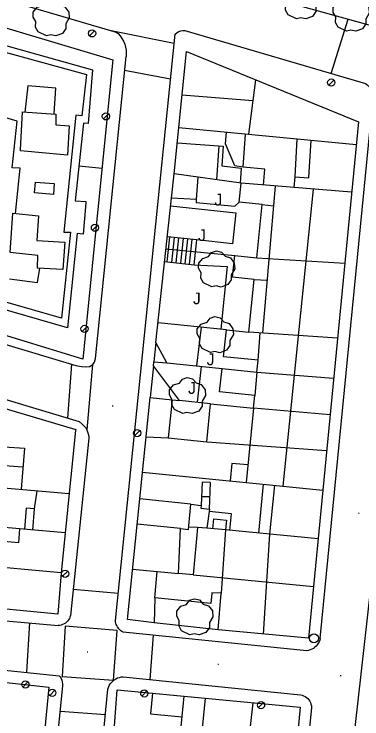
# Model space of a CAD drawing. Extents: x 431390 to 432653, y 4586754 to 4589600.
# Drawn here: x 432037.9 to 432076.5, y 4587457.3 to 4587535.4 of the extents above; entities that cross this region are included whole.
import ezdxf

# ---------------------------------------------------------------- set-up
doc = ezdxf.new("R2010")
doc.units = 0
for name, color, linetype in [('COM_17LS_LN', 7, 'Continuous'), ('COM_51_LN', 7, 'Continuous'), ('CON_01_LN', 7, 'Continuous'), ('CON_01FI_LN', 7, 'Continuous'), ('CON_03_LN', 7, 'Continuous'), ('CON_04_LN', 7, 'Continuous'), ('CON_07_LN', 7, 'Continuous'), ('CON_16_LN', 7, 'Continuous'), ('CON_23_LN', 7, 'Continuous'), ('CON_29_LN', 7, 'Continuous'), ('ENE_05_PT', 7, 'Continuous'), ('ENE_06_PT', 7, 'Continuous'), ('ORO_03_PT', 7, 'Continuous'), ('TOP_15JA_TX', 7, 'Continuous'), ('VEG_03_PT', 7, 'Continuous'), ('VEG_06_LN', 7, 'Continuous')]:
    doc.layers.add(name, color=color, linetype=linetype)

msp = doc.modelspace()

# ---------------------------------------------------------------- linework, layer by layer
at = {"layer": 'COM_17LS_LN'}
for points in [[(432021.761, 4587589.102), (432009.412, 4587553.409), (432035.816, 4587545.686), (432076.824, 4587534.291), (432119.906, 4587522.114), (432137.525, 4587517.191)], [(432010.743, 4587544.715), (432049.243, 4587533.403)], [(432049.175, 4587468.233), (432055.778, 4587533.151)], [(432049.243, 4587533.403), (432049.454, 4587533.22), (432049.687, 4587532.965), (432049.89, 4587532.684), (432050.058, 4587532.382), (432050.191, 4587532.062), (432050.287, 4587531.729), (432050.343, 4587531.388), (432050.36, 4587531.042), (432050.337, 4587530.697)], [(432055.778, 4587533.151), (432056.002, 4587533.342), (432056.194, 4587533.45), (432056.4, 4587533.528), (432056.616, 4587533.573), (432056.836, 4587533.585), (432076.863, 4587527.703), (432077.051, 4587527.55), (432077.223, 4587527.38), (432077.377, 4587527.193), (432077.51, 4587526.991), (432077.623, 4587526.776), (432077.713, 4587526.551), (432077.725, 4587526.51)], [(431996.838, 4587510.864), (432044.798, 4587496.474), (432045.397, 4587496.361), (432045.812, 4587496.304), (432046.282, 4587496.361), (432046.659, 4587496.586), (432046.847, 4587496.849), (432046.96, 4587497.259), (432050.337, 4587530.697)], [(432071.855, 4587466.252), (432077.725, 4587526.51)], [(432082.391, 4587522.854), (432077.771, 4587475.107), (432071.841, 4587422.243)], [(431994.834, 4587505.359), (432045.157, 4587490.258)], [(432045.157, 4587490.258), (432045.487, 4587489.974), (432045.922, 4587489.521), (432046.115, 4587489.025), (432046.207, 4587488.641), (432046.226, 4587488.417), (432044.177, 4587468.766), (432044.129, 4587468.602), (432044.062, 4587468.446), (432043.976, 4587468.299), (432043.873, 4587468.163), (432043.755, 4587468.041), (432043.622, 4587467.935), (432043.477, 4587467.845), (432043.323, 4587467.774), (432043.16, 4587467.722), (432042.993, 4587467.691), (432042.824, 4587467.68)], [(431983.87, 4587473.266), (432026.224, 4587469.135), (432042.824, 4587467.68)], [(431935.823, 4587472.596), (431974.184, 4587468.984), (431989.678, 4587467.644), (432042.941, 4587462.114)], [(432071.855, 4587466.252), (432071.799, 4587466.062), (432071.724, 4587465.879), (432071.629, 4587465.706), (432071.516, 4587465.544), (432071.386, 4587465.395), (432071.241, 4587465.261), (432071.082, 4587465.144), (432070.911, 4587465.044), (432070.731, 4587464.963), (432070.543, 4587464.903), (432070.35, 4587464.863), (432050.02, 4587466.945), (432049.891, 4587467.016), (432049.77, 4587467.099), (432049.658, 4587467.194), (432049.555, 4587467.299), (432049.463, 4587467.413), (432049.383, 4587467.536), (432049.315, 4587467.666), (432049.259, 4587467.802), (432049.217, 4587467.942), (432049.189, 4587468.086), (432049.175, 4587468.233)], [(432042.941, 4587462.114), (432043.042, 4587461.98), (432043.142, 4587461.806), (432043.221, 4587461.622), (432043.277, 4587461.429), (432043.31, 4587461.231), (432043.319, 4587461.031), (432039.699, 4587424.568)], [(432044.808, 4587424.287), (432048.33, 4587460.622), (432048.393, 4587460.825), (432048.481, 4587461.02), (432048.59, 4587461.204), (432048.721, 4587461.373), (432048.87, 4587461.526), (432049.036, 4587461.66), (432049.217, 4587461.774), (432049.41, 4587461.866), (432049.612, 4587461.934), (432049.821, 4587461.979), (432050.034, 4587461.999), (432069.658, 4587460.008), (432069.836, 4587459.966), (432070.008, 4587459.903), (432070.171, 4587459.818), (432070.322, 4587459.713), (432070.458, 4587459.591), (432070.578, 4587459.452), (432070.68, 4587459.299), (432070.761, 4587459.134), (432070.821, 4587458.961), (432070.859, 4587458.781), (432070.874, 4587458.599), (432067.323, 4587422.384)]]:
    msp.add_lwpolyline(points, dxfattribs=at)
at = {"layer": 'COM_51_LN'}
for points in [[(432073.041, 4587528.825), (432074.931, 4587534.817)], [(432048.688, 4587533.566), (432055.676, 4587532.153)], [(432055.274, 4587528.192), (432050.18, 4587529.143)], [(432043.897, 4587490.636), (432044.354, 4587496.607)], [(432046.63, 4587496.569), (432045.99, 4587489.354)], [(432044.482, 4587471.694), (432049.484, 4587471.269)], [(432039.669, 4587467.957), (432039.326, 4587462.489)], [(432048.941, 4587461.612), (432049.35, 4587467.114), (432043.608, 4587467.602), (432043.258, 4587462.029), (432048.941, 4587461.612)], [(432053.327, 4587466.606), (432052.963, 4587461.702)], [(432048.054, 4587457.779), (432043.033, 4587458.148)]]:
    msp.add_lwpolyline(points, dxfattribs=at)
at = {"layer": 'CON_01_LN'}
for points in [[(432035.619, 4587534.268), (432048.892, 4587530.32), (432045.544, 4587497.173), (432031.56, 4587501.469)], [(432055.663, 4587517.693), (432057.042, 4587531.234), (432076.068, 4587523.455), (432070.547, 4587466.266), (432060.533, 4587467.183)], [(432027.902, 4587470.378), (431998.966, 4587473.199), (431984.692, 4587474.591), (431995.054, 4587504.269), (431995.264, 4587504.196), (432008.448, 4587500.086), (432008.619, 4587500.012), (432028.206, 4587494.292), (432044.77, 4587489.367), (432044.755, 4587489.272), (432043.155, 4587473.509)], [(432053.437, 4587467.955), (432050.492, 4587468.349), (432053, 4587492.935)], [(431937.039, 4587471.608), (431974.708, 4587467.928), (431998.671, 4587465.624), (432030.718, 4587462.07), (432041.801, 4587460.863), (432038.233, 4587424.052), (432038.118, 4587424.066), (431961.949, 4587432.109), (431932.956, 4587435.141)], [(432048.406, 4587447.515), (432049.373, 4587460.546), (432069.632, 4587458.628), (432066.166, 4587421.562), (432050.714, 4587423.11)]]:
    msp.add_lwpolyline(points, dxfattribs=at)
at = {"layer": 'CON_01FI_LN'}
for points in [[(432053, 4587492.935), (432055.444, 4587492.685), (432055.011, 4587488.453), (432059.273, 4587488.016), (432059.706, 4587492.239), (432064.443, 4587491.753), (432064.585, 4587493.145), (432060.703, 4587493.541), (432060.967, 4587496.131), (432064.839, 4587495.736), (432064.973, 4587497.055), (432061.145, 4587497.443), (432061.447, 4587500.429), (432063.954, 4587500.175), (432064.544, 4587505.998), (432062.136, 4587506.241), (432062.378, 4587508.646), (432064.834, 4587508.398), (432065.429, 4587514.291), (432062.884, 4587514.547), (432063.095, 4587516.651), (432055.663, 4587517.693)], [(432056.134, 4587473.425), (432056.383, 4587478.432), (432057.242, 4587478.323), (432057.534, 4587481.099), (432058.663, 4587480.98), (432058.629, 4587480.665), (432059.576, 4587480.562), (432059.272, 4587478.46), (432058.259, 4587478.543), (432057.784, 4587473.281), (432056.134, 4587473.425)], [(432043.155, 4587473.509), (432033.43, 4587474.408)], [(432060.533, 4587467.183), (432060.857, 4587471.26), (432059.825, 4587471.281), (432059.825, 4587471.245), (432059.736, 4587470.121), (432053.518, 4587470.749), (432053.437, 4587467.955)]]:
    msp.add_lwpolyline(points, dxfattribs=at)
at = {"layer": 'CON_03_LN'}
for points in [[(432064.668, 4587528.116), (432063.888, 4587522.074)], [(432056.184, 4587522.811), (432075.824, 4587520.932)], [(432075.315, 4587515.66), (432063.095, 4587516.651)], [(432064.834, 4587508.398), (432074.556, 4587507.797)], [(432073.754, 4587499.484), (432063.954, 4587500.175)], [(432064.839, 4587495.736), (432073.326, 4587495.057)], [(432072.935, 4587491.006), (432064.443, 4587491.753)], [(432052.553, 4587488.553), (432055.011, 4587488.453)], [(432059.273, 4587488.016), (432072.554, 4587487.054)], [(432052.155, 4587484.648), (432072.131, 4587482.679)], [(432032.9, 4587483.262), (432044.047, 4587482.295)], [(432043.603, 4587477.921), (432033.88, 4587478.787)], [(432056.383, 4587478.432), (432051.567, 4587478.892)], [(432061.357, 4587478.26), (432059.272, 4587478.46)], [(432071.61, 4587477.274), (432061.357, 4587478.26)], [(432051.06, 4587473.922), (432056.134, 4587473.425)], [(432057.784, 4587473.281), (432071.1, 4587471.993)], [(432058.305, 4587451.102), (432059.152, 4587459.62)]]:
    msp.add_lwpolyline(points, dxfattribs=at)
at = {"layer": 'CON_04_LN'}
for points in [[(432034.465, 4587532.621), (432046.638, 4587529.219), (432046.146, 4587523.272), (432045.646, 4587523.325), (432044.701, 4587514.709), (432044.747, 4587514.706), (432045.873, 4587514.646), (432045.889, 4587514.502), (432045.591, 4587511.015), (432044.946, 4587511.077), (432043.851, 4587500.648), (432031.568, 4587504.2)], [(432034.384, 4587531.865), (432045.953, 4587528.689), (432045.457, 4587524.121), (432044.769, 4587524.181), (432043.465, 4587511.241), (432044.207, 4587511.246), (432043.198, 4587501.704), (432037.023, 4587503.479)], [(432042.386, 4587524.328), (432042.563, 4587527.173), (432039.48, 4587527.432), (432039.129, 4587524.531)], [(432038.101, 4587513.299), (432038.607, 4587518.313), (432038.57, 4587518.326), (432037.748, 4587518.361), (432038.272, 4587523.537), (432033.64, 4587524.908)], [(432043.847, 4587519.777), (432038.644, 4587520.252), (432038.645, 4587520.356), (432038.867, 4587524.547), (432042.584, 4587524.316), (432042.569, 4587524.268), (432042.582, 4587523.12), (432044.046, 4587523.021), (432043.847, 4587519.777)], [(432063.303, 4587518.434), (432062.391, 4587518.583), (432061.357, 4587521.031), (432061.461, 4587522.306)], [(432065.566, 4587516.451), (432065.708, 4587518.227), (432063.303, 4587518.434), (432063.583, 4587522.103)], [(432069.27, 4587521.559), (432069.023, 4587517.359), (432070.578, 4587517.242), (432070.838, 4587521.409)], [(432056.015, 4587521.145), (432061.08, 4587520.771), (432060.957, 4587518.577), (432063.099, 4587518.342), (432062.967, 4587516.669)], [(432060.622, 4587520.805), (432060.369, 4587517.033)], [(432045.125, 4587518.571), (432047.68, 4587518.316)], [(432069.023, 4587517.359), (432068.927, 4587516.178)], [(432040.298, 4587516.784), (432042.397, 4587516.626), (432042.306, 4587515.424), (432040.207, 4587515.581), (432040.298, 4587516.784)], [(432066.872, 4587516.345), (432065.459, 4587500.069)], [(432065.429, 4587514.291), (432066.682, 4587514.159)], [(432037.497, 4587508.973), (432037.823, 4587513.327), (432040.644, 4587513.04), (432040.468, 4587510.326), (432043.578, 4587510.138), (432043.341, 4587507.102), (432040.52, 4587507.253), (432040.584, 4587508.65), (432037.497, 4587508.973)], [(432037.445, 4587506.074), (432040.521, 4587505.672), (432040.813, 4587507.237)], [(432064.544, 4587505.998), (432065.968, 4587505.931)], [(432064.973, 4587497.055), (432065.186, 4587500.088)], [(432064.839, 4587495.736), (432064.585, 4587493.145)], [(432064.443, 4587491.753), (432063.653, 4587483.515)], [(432034.553, 4587487.592), (432039.092, 4587487.299), (432038.72, 4587482.757)], [(432033.803, 4587485.628), (432038.924, 4587485.253)], [(432063.839, 4587485.451), (432062.06, 4587485.622), (432061.873, 4587483.69)], [(432059.576, 4587480.562), (432059.705, 4587483.503), (432058.778, 4587483.543), (432058.663, 4587480.98)], [(432065.535, 4587483.329), (432065.011, 4587477.909)], [(432066.785, 4587483.206), (432066.225, 4587477.792)], [(432040.219, 4587480.579), (432040.506, 4587482.602)], [(432057.534, 4587481.099), (432051.855, 4587481.71)], [(432058.707, 4587481.956), (432059.638, 4587481.974)], [(432040.012, 4587478.241), (432040.219, 4587480.579), (432040.17, 4587480.6), (432039.273, 4587480.679), (432039.09, 4587478.323)], [(432061.834, 4587478.214), (432062.011, 4587480.052), (432059.537, 4587480.289)], [(432059.963, 4587478.394), (432060.068, 4587479.482), (432061.448, 4587479.348), (432061.357, 4587478.26)], [(432038.557, 4587478.37), (432038.42, 4587476.829), (432036.804, 4587476.972), (432036.94, 4587478.514)], [(432061.357, 4587478.26), (432060.857, 4587471.26)], [(432053.518, 4587470.749), (432053.791, 4587473.654)], [(432053.273, 4587460.177), (432053.056, 4587457.878), (432056.508, 4587457.552)], [(432056.726, 4587459.85), (432056.407, 4587456.48), (432058.811, 4587456.19)]]:
    msp.add_lwpolyline(points, dxfattribs=at)
at = {"layer": 'CON_07_LN'}
for points in [[(432058.302, 4587517.323), (432058.097, 4587514.848), (432055.372, 4587514.989), (432055.663, 4587517.693)], [(432053.425, 4587496.892), (432054.853, 4587496.779), (432053.655, 4587499.032), (432053.425, 4587496.892)], [(432055.444, 4587492.685), (432056.258, 4587492.588), (432053.375, 4587496.43), (432053, 4587492.935)]]:
    msp.add_lwpolyline(points, dxfattribs=at)
at = {"layer": 'CON_16_LN'}
for points in [[(432053.655, 4587499.032), (432055.372, 4587514.989)], [(432054.77, 4587509.396), (432062.378, 4587508.646)], [(432061.447, 4587500.429), (432053.886, 4587501.183)], [(432053.375, 4587496.43), (432053.425, 4587496.892)], [(432054.853, 4587496.779), (432060.967, 4587496.131)], [(432059.706, 4587492.239), (432056.258, 4587492.588)], [(432058.259, 4587478.543), (432057.266, 4587478.547)], [(432043.155, 4587473.509), (432042.773, 4587468.933), (432027.902, 4587470.378)], [(432060.533, 4587467.183), (432053.437, 4587467.955)]]:
    msp.add_lwpolyline(points, dxfattribs=at)
at = {"layer": 'CON_23_LN'}
for points in [[(432054.9, 4587507.947), (432055.196, 4587510.7)], [(432058.178, 4587510.379), (432054.914, 4587510.731)], [(432055.397, 4587507.894), (432055.693, 4587510.647)], [(432055.894, 4587507.84), (432056.19, 4587510.593)], [(432056.391, 4587507.787), (432056.687, 4587510.54)], [(432056.888, 4587507.733), (432057.184, 4587510.486)], [(432057.385, 4587507.68), (432057.681, 4587510.433)], [(432057.882, 4587507.626), (432058.178, 4587510.379)], [(432054.618, 4587507.978), (432057.882, 4587507.626)]]:
    msp.add_lwpolyline(points, dxfattribs=at)
at = {"layer": 'CON_29_LN'}
for points in [[(432064.369, 4587525.799), (432056.55, 4587526.402)], [(432067.747, 4587483.111), (432071.102, 4587516.002)], [(432066.225, 4587477.792), (432065.509, 4587466.727)], [(432063.461, 4587450.601), (432064.434, 4587459.12)]]:
    msp.add_lwpolyline(points, dxfattribs=at)
at = {"layer": 'ENE_05_PT'}
msp.add_circle((432071.139, 4587466.247), 0.5, dxfattribs=at)
at = {"layer": 'ENE_06_PT'}
for p, q in [((432046.864, 4587533.534), (432046.298, 4587532.968)), ((432073.349, 4587528.084), (432072.783, 4587527.518)), ((432048.393, 4587524.342), (432047.827, 4587523.776)), ((432047.186, 4587512.012), (432046.62, 4587511.446)), ((432046.035, 4587500.803), (432045.469, 4587500.237)), ((432051.865, 4587489.269), (432051.299, 4587488.703)), ((432043.889, 4587473.687), (432043.323, 4587473.121)), ((432039.474, 4587461.429), (432038.908, 4587460.863)), ((432042.45, 4587460.495), (432041.884, 4587459.929)), ((432052.644, 4587460.433), (432052.078, 4587459.867)), ((432065.571, 4587459.142), (432065.005, 4587458.576))]:
    msp.add_line(p, q, dxfattribs=at)
for centre in [(432046.581, 4587533.251), (432073.066, 4587527.801), (432048.11, 4587524.059), (432046.903, 4587511.729), (432045.752, 4587500.52), (432051.582, 4587488.986), (432043.606, 4587473.404), (432039.191, 4587461.146), (432042.167, 4587460.212), (432052.361, 4587460.15), (432065.288, 4587458.859)]:
    msp.add_circle(centre, 0.4, dxfattribs=at)
at = {"layer": 'ORO_03_PT'}
for p, q in [((432048.818, 4587491.989), (432048.918, 4587491.989)), ((432076.074, 4587480.117), (432076.174, 4587480.117)), ((432046.025, 4587464.75), (432046.125, 4587464.75)), ((432060.497, 4587463.4), (432060.597, 4587463.4)), ((432074.069, 4587462.136), (432074.169, 4587462.136))]:
    msp.add_line(p, q, dxfattribs=at)
at = {"layer": 'VEG_03_PT'}
for points in [[(432069.212, 4587534.865), (432068.285, 4587535.3), (432067.997, 4587535.821), (432068.02, 4587536.435), (432067.738, 4587536.927), (432067.746, 4587537.49), (432068.187, 4587538.025), (432068.84, 4587538.229), (432069.175, 4587538.68), (432069.701, 4587538.85), (432070.281, 4587538.717), (432070.681, 4587538.251), (432071.255, 4587538.081), (432071.689, 4587537.498), (432071.738, 4587536.856), (432071.355, 4587536.209), (432071.355, 4587535.659), (432070.983, 4587535.125), (432070.244, 4587534.85), (432069.679, 4587534.978), (432069.212, 4587534.865)], [(432041.535, 4587532.98), (432040.608, 4587533.415), (432040.32, 4587533.936), (432040.343, 4587534.55), (432040.061, 4587535.042), (432040.069, 4587535.605), (432040.51, 4587536.14), (432041.163, 4587536.344), (432041.498, 4587536.795), (432042.024, 4587536.965), (432042.604, 4587536.832), (432043.004, 4587536.366), (432043.578, 4587536.196), (432044.012, 4587535.613), (432044.061, 4587534.971), (432043.678, 4587534.324), (432043.678, 4587533.774), (432043.306, 4587533.24), (432042.567, 4587532.965), (432042.002, 4587533.093), (432041.535, 4587532.98)], [(432074.749, 4587533.498), (432073.822, 4587533.933), (432073.534, 4587534.454), (432073.557, 4587535.068), (432073.275, 4587535.56), (432073.283, 4587536.123), (432073.724, 4587536.658), (432074.377, 4587536.862), (432074.712, 4587537.313), (432075.238, 4587537.483), (432075.818, 4587537.35), (432076.218, 4587536.884), (432076.792, 4587536.714), (432077.226, 4587536.131), (432077.275, 4587535.489), (432076.892, 4587534.842), (432076.892, 4587534.292), (432076.52, 4587533.758), (432075.781, 4587533.483), (432075.216, 4587533.611), (432074.749, 4587533.498)], [(432059.855, 4587505.176), (432058.928, 4587505.611), (432058.64, 4587506.132), (432058.663, 4587506.746), (432058.381, 4587507.238), (432058.389, 4587507.801), (432058.83, 4587508.336), (432059.483, 4587508.54), (432059.818, 4587508.991), (432060.344, 4587509.161), (432060.924, 4587509.028), (432061.324, 4587508.562), (432061.898, 4587508.392), (432062.332, 4587507.809), (432062.381, 4587507.167), (432061.998, 4587506.52), (432061.998, 4587505.97), (432061.626, 4587505.436), (432060.887, 4587505.161), (432060.322, 4587505.289), (432059.855, 4587505.176)], [(432059.7, 4587497.904), (432058.773, 4587498.339), (432058.485, 4587498.86), (432058.508, 4587499.474), (432058.226, 4587499.966), (432058.234, 4587500.529), (432058.675, 4587501.064), (432059.328, 4587501.268), (432059.663, 4587501.719), (432060.189, 4587501.889), (432060.769, 4587501.756), (432061.169, 4587501.29), (432061.743, 4587501.12), (432062.177, 4587500.537), (432062.226, 4587499.895), (432061.843, 4587499.248), (432061.843, 4587498.698), (432061.471, 4587498.164), (432060.732, 4587497.889), (432060.167, 4587498.017), (432059.7, 4587497.904)], [(432056.62, 4587491.159), (432055.693, 4587491.594), (432055.405, 4587492.115), (432055.428, 4587492.729), (432055.146, 4587493.221), (432055.154, 4587493.784), (432055.595, 4587494.319), (432056.248, 4587494.523), (432056.583, 4587494.974), (432057.109, 4587495.144), (432057.689, 4587495.011), (432058.089, 4587494.545), (432058.663, 4587494.375), (432059.097, 4587493.792), (432059.146, 4587493.15), (432058.763, 4587492.503), (432058.763, 4587491.953), (432058.391, 4587491.419), (432057.652, 4587491.144), (432057.087, 4587491.272), (432056.62, 4587491.159)], [(432057.422, 4587466.649), (432056.495, 4587467.084), (432056.207, 4587467.605), (432056.23, 4587468.219), (432055.948, 4587468.711), (432055.956, 4587469.274), (432056.397, 4587469.809), (432057.05, 4587470.013), (432057.385, 4587470.464), (432057.911, 4587470.634), (432058.491, 4587470.501), (432058.891, 4587470.035), (432059.465, 4587469.865), (432059.899, 4587469.282), (432059.948, 4587468.64), (432059.565, 4587467.993), (432059.565, 4587467.443), (432059.193, 4587466.909), (432058.454, 4587466.634), (432057.889, 4587466.762), (432057.422, 4587466.649)]]:
    msp.add_lwpolyline(points, dxfattribs=at)
at = {"layer": 'VEG_06_LN'}
for points in [[(432058.097, 4587514.848), (432058.104, 4587514.51), (432062.37, 4587514.111), (432062.884, 4587514.547)], [(432055.281, 4587514.146), (432062.487, 4587513.371), (432062.119, 4587509.955), (432058.178, 4587510.379)], [(432057.882, 4587507.626), (432061.549, 4587507.415), (432060.855, 4587500.488)], [(432058.663, 4587500.707), (432058.154, 4587496.429)], [(432058.676, 4587496.374), (432058.199, 4587492.392)]]:
    msp.add_lwpolyline(points, dxfattribs=at)

# ---------------------------------------------------------------- texts
at = {"layer": 'TOP_15JA_TX'}
for p in [(432060.126, 4587514.183), (432058.322, 4587510.262), (432057.748, 4587503.252), (432059.263, 4587496.501), (432057.206, 4587493.326)]:
    msp.add_text('J', height=1.3, dxfattribs=at).set_placement(p)

doc.saveas('drawing.dxf')
